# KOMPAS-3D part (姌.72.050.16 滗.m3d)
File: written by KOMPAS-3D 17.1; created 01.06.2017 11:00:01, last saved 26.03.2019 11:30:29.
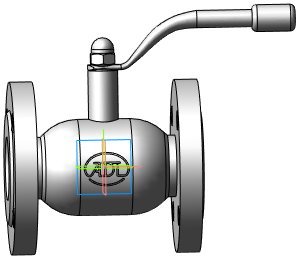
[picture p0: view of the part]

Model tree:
1. Операция без истории:2  (labels: Сталь 20  ГОСТ 1050-88)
